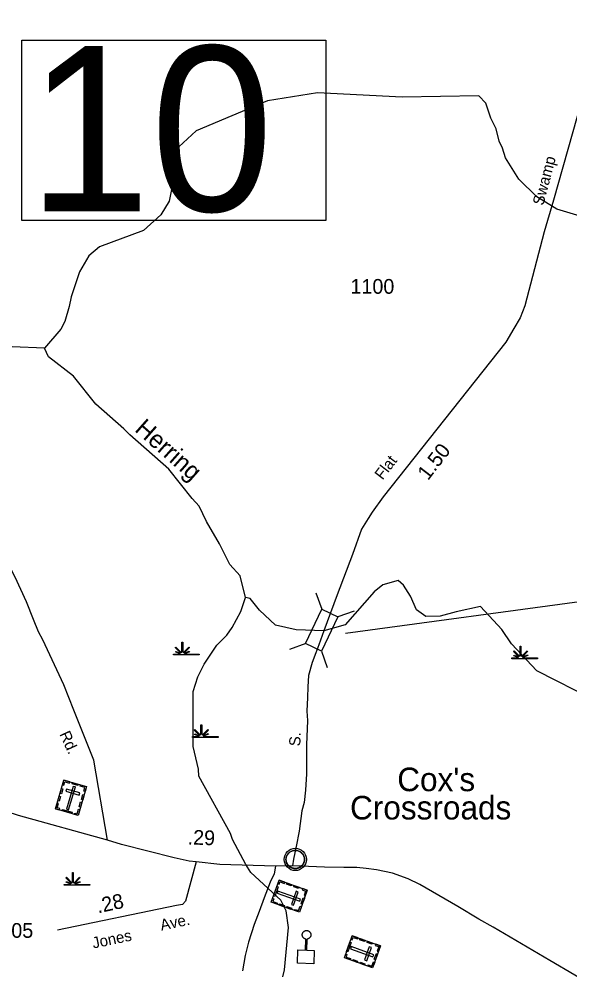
# Model space of a CAD drawing. Extents: x 2532689 to 2764727, y 536648 to 732970.
# Drawn here: x 2608460 to 2613131, y 594925 to 602992 of the extents above; entities that cross this region are included whole.
import ezdxf

# ---------------------------------------------------------------- set-up
doc = ezdxf.new("R2010")
doc.units = 0
for name, color, linetype in [('Exist Civil Demographics Community CELL', 7, 'Continuous'), ('Exist Civil Demographics Community Label', 7, 'Continuous'), ('Exist Civil Post Office CELL', 7, 'Continuous'), ('Exist Cultural Cemetery CELL', 7, 'Continuous'), ('Exist Hydrographic Creek Single Shore', 7, 'Continuous'), ('Exist Hydrographic Creek Single Shore Label', 7, 'Continuous'), ('Exist Hydrographic Swamp CELL', 7, 'Continuous'), ('Exist Road Primary NC Attributed', 7, 'Continuous'), ('Exist Road Primary NC Mileage Hundredths English Label', 7, 'Continuous'), ('Exist Road Secondary Mileage Hundredths English Label', 7, 'Continuous'), ('Exist Road Secondary Structure Standard Bridge CELL', 7, 'Continuous'), ('Exist Road Secondary Structure Standard Bridge Number Label', 7, 'Continuous'), ('Exist Road Secondary Type 10 Attributed', 7, 'Continuous'), ('Exist Road Secondary Type 51 Attributed', 7, 'Continuous'), ('Exist Road Secondary Type 51 Label', 7, 'Continuous'), ('Exist Road Secondary Type 51 Number Label', 7, 'Continuous')]:
    doc.layers.add(name, color=color, linetype=linetype)

msp = doc.modelspace()

# ---------------------------------------------------------------- linework, layer by layer
at = {"layer": 'Exist Civil Demographics Community CELL'}
msp.add_lwpolyline([(2610724.5, 595874.9), (2610725.5, 595880.5), (2610727.2, 595887.1), (2610730.2, 595894.3), (2610733.1, 595900), (2610736.4, 595905.7), (2610740.2, 595910.9), (2610744.1, 595915.2), (2610748.7, 595919.8), (2610754.3, 595924.4), (2610759.7, 595928.1), (2610764.6, 595930.9), (2610769.6, 595933.4), (2610775.1, 595935.7), (2610780.7, 595937.5), (2610785, 595938.7), (2610789.9, 595939.4), (2610794, 595940.1), (2610800.4, 595940.4), (2610804.8, 595940.3), (2610810.5, 595940), (2610815.4, 595939.3), (2610820.3, 595938.3), (2610825.3, 595936.9), (2610830.5, 595935), (2610837.1, 595932), (2610843.4, 595928.5), (2610848.4, 595925), (2610853.6, 595921), (2610856.9, 595917.9), (2610861, 595913.5), (2610864.9, 595908.8), (2610868, 595904.2), (2610871.1, 595899.2), (2610873.6, 595894), (2610875.6, 595889), (2610877.2, 595884), (2610878.4, 595879.4), (2610879.5, 595873.3), (2610880.2, 595868.6), (2610880.4, 595862.6), (2610880.2, 595856.9), (2610879.7, 595851.2), (2610878.7, 595845.7), (2610877.1, 595839.5), (2610875.2, 595833.7), (2610872.9, 595828.6), (2610869.8, 595822.6), (2610866.5, 595817.3), (2610863, 595812.6), (2610858.8, 595807.9), (2610853.5, 595802.9), (2610848.5, 595798.8), (2610843.5, 595795.3), (2610839.2, 595792.8), (2610832.3, 595789.6), (2610825.2, 595786.9), (2610819.2, 595785.4), (2610812.6, 595784.1), (2610808.2, 595783.6), (2610803.7, 595783.4), (2610798.1, 595783.4), (2610793.9, 595783.8), (2610788.2, 595784.5), (2610782.3, 595785.8), (2610777.7, 595787.1), (2610772.5, 595789), (2610768, 595791), (2610764, 595793.2), (2610757.2, 595797.3), (2610751.7, 595801.6), (2610746.7, 595806.1), (2610742.3, 595810.9), (2610739.1, 595814.9), (2610736.1, 595819.1), (2610732, 595826.2), (2610730.3, 595829.7), (2610728.6, 595833.7), (2610726, 595841.9), (2610724.5, 595849), (2610723.8, 595854.1), (2610723.4, 595860.5), (2610723.4, 595865.1), (2610723.9, 595871.6)], close=True, dxfattribs=at)
for centre, radius in [((2610802.1, 595862.5), 94.3), ((2610801.8, 595862.8), 76.7)]:
    msp.add_circle(centre, radius, dxfattribs=at)
at = {"layer": 'Exist Civil Post Office CELL'}
msp.add_lwpolyline([(2610892.7, 595186.9), (2610890, 595187.4), (2610887.2, 595188.1), (2610884.4, 595189.1), (2610881.8, 595190.2), (2610879.5, 595191.5), (2610877.5, 595192.8), (2610875.7, 595194), (2610873.6, 595195.8), (2610872.1, 595197.2), (2610870.5, 595199), (2610869, 595200.8), (2610867.7, 595202.5), (2610866.5, 595204.5), (2610865.4, 595206.6), (2610864.5, 595208.5), (2610863.6, 595210.4), (2610863.1, 595212.1), (2610862.5, 595214.1), (2610862, 595216.4), (2610861.7, 595218.5), (2610861.5, 595220.6), (2610861.5, 595222.9), (2610861.5, 595225.6), (2610861.8, 595227.8), (2610862.1, 595230), (2610862.7, 595232.6), (2610863.3, 595234.5), (2610864, 595236.5), (2610864.8, 595238.3), (2610865.6, 595239.9), (2610866.6, 595241.7), (2610867.8, 595243.5), (2610869.1, 595245.4), (2610871.2, 595247.8), (2610873, 595249.6), (2610874.7, 595251.1), (2610876.3, 595252.3), (2610877.9, 595253.5), (2610879.9, 595254.7), (2610881.7, 595255.7), (2610884, 595256.7), (2610886.2, 595257.5), (2610889.1, 595258.4), (2610891.7, 595258.9), (2610894.5, 595259.4), (2610897.2, 595259.5), (2610899.2, 595259.4), (2610902.1, 595259.3), (2610905, 595258.8), (2610907.6, 595258.2), (2610909.8, 595257.5), (2610911.8, 595256.7), (2610914.3, 595255.6), (2610916.5, 595254.4), (2610918.8, 595252.9), (2610921, 595251.3), (2610923.2, 595249.3), (2610925.1, 595247.4), (2610926.6, 595245.6), (2610927.7, 595244.1), (2610929.3, 595241.5), (2610930.4, 595239.6), (2610931.4, 595237.5), (2610932.2, 595235.4), (2610932.9, 595233.2), (2610933.6, 595230.7), (2610933.9, 595228.4), (2610934.3, 595225.7), (2610934.4, 595223.6), (2610934.4, 595221.3), (2610934.2, 595218.9), (2610933.9, 595216.9), (2610933.4, 595214.3), (2610932.7, 595212), (2610931.9, 595209.7), (2610931, 595207.5), (2610929.9, 595205.3), (2610928.6, 595203.2), (2610926.9, 595200.7), (2610925.3, 595198.9), (2610923.5, 595196.9), (2610921.1, 595194.8), (2610919.2, 595193.3), (2610917.4, 595192.1), (2610915, 595190.7), (2610912.8, 595189.7), (2610910.5, 595188.7), (2610908.6, 595188.1), (2610906.3, 595187.4), (2610903.7, 595186.9), (2610902, 595186.7), (2610900.7, 595186.6), (2610897.6, 595093.2), (2610963.1, 595091), (2610959.3, 594977.6), (2610820.3, 594982.3), (2610824, 595095.7), (2610889.6, 595093.5)], close=True, dxfattribs=at)
at = {"layer": 'Exist Cultural Cemetery CELL'}
for points in [[(2608841.1, 596536), (2609032.2, 596480.1), (2608960.7, 596235.7), (2608769.6, 596291.6)], [(2608828.9, 596494.4), (2608839.8, 596491.3), (2608848.9, 596522.2), (2608887.8, 596510.8), (2608890.9, 596521.4), (2608841.1, 596536)], [(2608912.2, 596515.2), (2608961.9, 596500.7), (2608958.7, 596489.7), (2608909, 596504.3)], [(2608808.1, 596423.3), (2608820.3, 596464.9), (2608831.2, 596461.7), (2608819, 596420.1)], [(2608861.2, 596459.2), (2608855.9, 596441.3), (2608968.9, 596408.3), (2608974.2, 596426.2)], [(2608937.5, 596477.3), (2608919.6, 596482.5), (2608862.6, 596287.9), (2608880.6, 596282.7)], [(2609020.1, 596438.5), (2609009.2, 596441.7), (2609018.2, 596472.6), (2608979.3, 596483.9), (2608982.4, 596494.6), (2609032.2, 596480.1)], [(2608789.2, 596358.8), (2608801.4, 596400.3), (2608812.3, 596397.1), (2608800.1, 596355.6)], [(2608970.1, 596308.3), (2608982.2, 596349.9), (2608993.1, 596346.7), (2608981, 596305.1)], [(2608988.6, 596371.6), (2609000.8, 596413.1), (2609011.7, 596409.9), (2608999.5, 596368.4)], [(2608801.4, 596282.4), (2608804.6, 596293.4), (2608783.5, 596299.6), (2608794.8, 596338.4), (2608784.1, 596341.5), (2608769.6, 596291.7)], [(2608828, 596286.5), (2608909.4, 596262.7), (2608906.2, 596251.8), (2608824.8, 596275.6)], [(2608928.9, 596245), (2608932.1, 596256.1), (2608953.2, 596249.9), (2608964.6, 596288.7), (2608975.3, 596285.5), (2608960.7, 596235.7)], [(2610904.4, 595601.4), (2610837.3, 595413.9), (2610597.6, 595499.7), (2610664.7, 595687.2)], [(2610656.1, 595629.2), (2610627.5, 595549.3), (2610616.8, 595553.1), (2610645.4, 595633)], [(2610653.6, 595656), (2610664.4, 595652.1), (2610671.8, 595672.8), (2610709.8, 595659.2), (2610713.6, 595669.7), (2610664.7, 595687.2)], [(2610730.5, 595663.6), (2610771.3, 595649), (2610767.5, 595638.3), (2610726.7, 595652.9)], [(2610793.8, 595641), (2610834.6, 595626.4), (2610830.8, 595615.6), (2610790, 595630.2)], [(2610840.1, 595508.6), (2610846.4, 595526.2), (2610655.4, 595594.5), (2610649.2, 595576.9)], [(2610826.6, 595585.9), (2610809, 595592.2), (2610769.3, 595481.3), (2610786.9, 595475)], [(2610863.6, 595616), (2610859.8, 595605.3), (2610890.1, 595594.4), (2610876.4, 595556.2), (2610886.9, 595552.5), (2610904.4, 595601.4)], [(2610608.7, 595530.9), (2610619.6, 595527), (2610612.1, 595506.3), (2610650.2, 595492.7), (2610646.4, 595482.2), (2610597.6, 595499.7)], [(2610669.5, 595486.1), (2610710.2, 595471.5), (2610706.4, 595460.8), (2610665.6, 595475.4)], [(2610731.5, 595463.8), (2610772.3, 595449.2), (2610768.5, 595438.5), (2610727.7, 595453.1)], [(2610796.5, 595428.5), (2610800.3, 595439.1), (2610830.6, 595428.3), (2610844.3, 595466.5), (2610854.7, 595462.7), (2610837.2, 595413.9)], [(2610879.4, 595531.6), (2610862, 595482.8), (2610851.2, 595486.7), (2610868.7, 595535.5)], [(2611525.2, 595129.8), (2611458.1, 594942.4), (2611218.4, 595028.2), (2611285.5, 595215.6)], [(2611276.9, 595157.6), (2611248.3, 595077.7), (2611237.6, 595081.6), (2611266.2, 595161.5)], [(2611274.4, 595184.5), (2611285.2, 595180.6), (2611292.6, 595201.3), (2611330.7, 595187.7), (2611334.4, 595198.2), (2611285.6, 595215.6)], [(2611351.3, 595192.1), (2611392.1, 595177.5), (2611388.3, 595166.8), (2611347.5, 595181.4)], [(2611414.6, 595169.4), (2611455.4, 595154.8), (2611451.6, 595144.1), (2611410.8, 595158.7)], [(2611484.4, 595144.4), (2611480.6, 595133.7), (2611510.9, 595122.9), (2611497.3, 595084.7), (2611507.7, 595080.9), (2611525.2, 595129.8)], [(2611229.6, 595059.4), (2611240.4, 595055.5), (2611233, 595034.8), (2611271, 595021.2), (2611267.3, 595010.7), (2611218.4, 595028.2)], [(2611460.9, 595037), (2611467.2, 595054.6), (2611276.3, 595123), (2611270, 595105.4)], [(2611447.4, 595114.3), (2611429.8, 595120.6), (2611390.1, 595009.8), (2611407.7, 595003.5)], [(2611500.2, 595060.1), (2611482.8, 595011.3), (2611472.1, 595015.1), (2611489.5, 595063.9)], [(2611290.3, 595014.5), (2611331.1, 594999.9), (2611327.2, 594989.2), (2611286.4, 595003.8)], [(2611352.3, 594992.3), (2611393.1, 594977.7), (2611389.3, 594967), (2611348.5, 594981.6)], [(2611417.3, 594956.9), (2611421.1, 594967.6), (2611451.4, 594956.7), (2611465.1, 594994.9), (2611475.6, 594991.2), (2611458.1, 594942.3)]]:
    msp.add_lwpolyline(points, close=True, dxfattribs=at)
at = {"layer": 'Exist Hydrographic Creek Single Shore'}
for points in [[(2613246.1, 601310.4), (2613019.1, 601380), (2612849.9, 601484.9), (2612697, 601633), (2612585, 601815.6), (2612557.9, 601896.6), (2612531.9, 601954.6), (2612505, 602061.9), (2612460.9, 602152.1), (2612416.9, 602278.3), (2612358, 602341.6), (2611708, 602328.4), (2610989.9, 602365.1), (2610565.9, 602298.7), (2609962.8, 602044.5), (2609815.8, 601907.2), (2609816.8, 601864.6), (2609734, 601447.5), (2609661, 601329.7), (2609513.9, 601199), (2609141.8, 601059.2), (2609052, 600983.3), (2608971.8, 600848.7), (2608900.8, 600635.7), (2608885.9, 600553), (2608846.9, 600426.7), (2608814.9, 600359.7), (2608676.9, 600199.9)], [(2608676.9, 600199.9), (2608400.9, 600211.7), (2607664.8, 600369.1), (2607356.8, 600330.4), (2606973.7, 600331.3), (2606705.8, 600359.8), (2606303.8, 600458.6), (2605992.8, 600593.8), (2605875.7, 600598.8)], [(2610379, 598085.3), (2610333.9, 598267.3), (2610248, 598365.7), (2610160.9, 598539.4), (2610048.9, 598728.6), (2609988, 598860.8), (2609927.9, 598924), (2609730.9, 599172.1), (2609399.9, 599464.1), (2609348.9, 599514.6), (2609110.8, 599725), (2608922.8, 599963.6), (2608710.9, 600125.7), (2608676.9, 600199.9)], [(2612553.8, 597813.8), (2612371.9, 598008.3), (2612165.1, 597963.8), (2612032, 597925.6), (2611907.9, 597923.9), (2611831, 597979.9), (2611778.9, 598095.9), (2611719.1, 598188.7), (2611676, 598229.7), (2611543.9, 598191.5), (2611469.9, 598132.7), (2611224.9, 597853.6), (2611043.6, 597802.8), (2610810.1, 597810.5), (2610633.9, 597849.4), (2610498, 597978.5), (2610420.9, 598077.1), (2610379, 598085.3)], [(2610220.7, 597765.2), (2610267.9, 597831.3), (2610339.9, 597965.6), (2610379, 598085.3)], [(2616087.3, 595239.6), (2615985.2, 595376.6), (2615663.2, 595596.8), (2615305.2, 595973), (2615202.1, 596119.8), (2614989.2, 596347.6), (2614726.2, 596560.3), (2614499.2, 596695.5), (2613920.1, 596875.7), (2613701.1, 596998.2), (2613338.2, 597213.3), (2612849.1, 597462.8), (2612636.1, 597690.6), (2612553.8, 597813.8)], [(2610656.1, 594708.2), (2610710, 594927.1), (2610744, 595286.3), (2610725, 595426.8), (2610681.1, 595516.9), (2610426, 595752.9), (2610382.9, 595820), (2610270, 596032.2), (2610252.9, 596084), (2609983.9, 596568.9), (2609982.9, 596627.9), (2609937, 596819.8), (2609935.9, 597286), (2609974.9, 597412.3), (2610030.9, 597519.7), (2610135.9, 597681.5), (2610220.7, 597765.2)]]:
    msp.add_lwpolyline(points, dxfattribs=at)
at = {"layer": 'Exist Hydrographic Swamp CELL'}
for points in [[(2609769.7, 597604.1), (2609822.3, 597604.1), (2609824.3, 597607.7), (2609786.1, 597622.6), (2609789, 597627.8), (2609826.7, 597612), (2609828.3, 597614.9), (2609783.9, 597659.4), (2609789, 597664.6), (2609834.3, 597619.1), (2609840.6, 597621.5), (2609840.6, 597704.6), (2609847.9, 597704.6), (2609847.8, 597621.5), (2609854.2, 597619.1), (2609899.5, 597664.6), (2609904.6, 597659.4), (2609860.2, 597614.9), (2609862.2, 597611.3), (2609903.1, 597629.9), (2609905.5, 597624.9), (2609864.6, 597607), (2609866.2, 597604.1), (2609987.2, 597604.1), (2609987.2, 597596.9), (2609769.7, 597596.9)], [(2612637.7, 597571.7), (2612690.3, 597571.8), (2612692.3, 597575.4), (2612654.1, 597590.2), (2612657, 597595.4), (2612694.7, 597579.6), (2612696.3, 597582.5), (2612651.9, 597627.1), (2612657, 597632.2), (2612702.3, 597586.7), (2612708.6, 597589.1), (2612708.6, 597672.2), (2612715.9, 597672.2), (2612715.9, 597589.1), (2612722.2, 597586.7), (2612767.5, 597632.2), (2612772.6, 597627.1), (2612728.2, 597582.5), (2612730.2, 597578.9), (2612771.1, 597597.5), (2612773.5, 597592.5), (2612732.6, 597574.7), (2612734.2, 597571.8), (2612855.2, 597571.7), (2612855.2, 597564.6), (2612637.7, 597564.6)], [(2609930.6, 596904.1), (2609983.2, 596904.2), (2609985.2, 596907.8), (2609947, 596922.6), (2609949.9, 596927.8), (2609987.6, 596912), (2609989.2, 596914.9), (2609944.8, 596959.5), (2609949.9, 596964.6), (2609995.2, 596919.1), (2610001.5, 596921.5), (2610001.5, 597004.6), (2610008.7, 597004.6), (2610008.7, 596921.5), (2610015.1, 596919.1), (2610060.4, 596964.6), (2610065.5, 596959.5), (2610021.1, 596914.9), (2610023.1, 596911.3), (2610064, 596929.9), (2610066.4, 596924.9), (2610025.4, 596907.1), (2610027, 596904.2), (2610148.1, 596904.1), (2610148.1, 596897), (2609930.6, 596897)], [(2608841.9, 595650.3), (2608894.5, 595650.4), (2608896.5, 595654), (2608858.2, 595668.8), (2608861.1, 595674), (2608898.9, 595658.3), (2608900.5, 595661.1), (2608856, 595705.7), (2608861.2, 595710.8), (2608906.4, 595665.3), (2608912.8, 595667.7), (2608912.8, 595750.8), (2608920, 595750.8), (2608920, 595667.7), (2608926.3, 595665.3), (2608971.6, 595710.8), (2608976.8, 595705.7), (2608932.3, 595661.1), (2608934.3, 595657.5), (2608975.2, 595676.1), (2608977.7, 595671.1), (2608936.7, 595653.3), (2608938.3, 595650.4), (2609059.4, 595650.3), (2609059.4, 595643.2), (2608841.9, 595643.2)]]:
    msp.add_lwpolyline(points, close=True, dxfattribs=at)
at = {"layer": 'Exist Road Primary NC Attributed'}
for points in [[(2609209, 596025.1), (2608455.4, 596236.7), (2607613, 596505.8)], [(2609962.7, 595841.6), (2609901.3, 595846.8), (2609775.4, 595874.8), (2609327.8, 595990.1), (2609209, 596025.1)], [(2610634.4, 595806.5), (2610162.3, 595819.9), (2609962.7, 595841.6)], [(2610780, 595809.6), (2610634.4, 595806.5)], [(2618622, 593002.4), (2615679, 593509), (2615482.1, 593555.2), (2615414.5, 593579.8), (2615214.6, 593678.2), (2614737.8, 593959.1), (2614095.5, 594337.4), (2613597.3, 594630.6), (2612960.1, 595005.8), (2612478.8, 595288.8), (2612359.9, 595356.5), (2612179.4, 595464.1), (2611858.5, 595648.6), (2611760.1, 595697.9), (2611626.3, 595745), (2611490, 595774.7), (2611402.8, 595786), (2611324.9, 595793.2), (2611212.7, 595795.3), (2611050.7, 595798.3), (2610780, 595809.6)]]:
    msp.add_lwpolyline(points, dxfattribs=at)
at = {"layer": 'Exist Road Secondary Structure Standard Bridge CELL'}
for p, q in [((2610977.7, 598124.1), (2611026.9, 597985.4)), ((2611301.4, 597969.9), (2611162.8, 597920.7)), ((2610890.8, 597693.3), (2610752.1, 597644.1)), ((2611023.6, 597630.1), (2611072.8, 597491.4))]:
    msp.add_line(p, q, dxfattribs=at)
msp.add_lwpolyline([(2611162.8, 597920.7), (2611024.2, 597629.8), (2610888.3, 597694.5), (2611026.9, 597985.4)], close=True, dxfattribs=at)
at = {"layer": 'Exist Road Secondary Structure Standard Bridge Number Label'}
msp.add_line((2611228.4, 597781.2), (2616649.6, 598515.7), dxfattribs=at)
msp.add_lwpolyline([(2608483.9, 602812.1), (2611060.5, 602812.1), (2611060.5, 601282.9), (2608483.9, 601282.9)], close=True, dxfattribs=at)
at = {"layer": 'Exist Road Secondary Type 10 Attributed'}
msp.add_lwpolyline([(2609962.7, 595841.6), (2609870.6, 595508.1), (2609847.1, 595481.5), (2609795.2, 595472.5), (2608785.3, 595261.3)], dxfattribs=at)
at = {"layer": 'Exist Road Secondary Type 51 Attributed'}
for points in [[(2613499, 602992.2), (2613423.2, 602902.6), (2613368.1, 602792.4), (2613192.5, 602165.2), (2612992.8, 601455.4), (2612913.6, 601186.7), (2612748.3, 600559.6), (2612710.4, 600456.2), (2612655.3, 600366.6), (2612586.4, 600249.5), (2611546.4, 598940.1), (2611453.4, 598809.2), (2611419, 598754), (2611363.9, 598664.5), (2611288.1, 598450.8), (2611157.3, 598106.3), (2611043.6, 597802.8)], [(2609209, 596025.1), (2609093.6, 596703.5), (2608925.5, 597130.1), (2608839.5, 597342.4), (2608660.5, 597724.6), (2608625.4, 597793.1), (2608582, 597897.2), (2608522.6, 598049), (2608428.2, 598257), (2608303.2, 598498.5), (2608042.8, 598897), (2607906, 599138.4), (2607822.4, 599218.4), (2607757.1, 599265), (2607693.8, 599329.8), (2607431.5, 599442.3), (2607282.5, 599489.5), (2607101.9, 599521.6), (2606765.8, 599616.7), (2606743.2, 599648.2), (2606690.8, 599739.5), (2606677, 599966.9), (2606683.9, 600159.9), (2606705.8, 600359.8)], [(2611043.6, 597802.8), (2611001.2, 597682), (2610976.7, 597615.3), (2610944.5, 597534.6), (2610914.8, 597424), (2610908.6, 597325.9), (2610904.7, 597235.8), (2610901.1, 597121.7), (2610906.3, 597042), (2610897.7, 596833.4), (2610897.7, 596707.7), (2610897.7, 596587.6), (2610889.2, 596450.5), (2610877.7, 596344.7), (2610858.5, 596274.6), (2610834.9, 596101.8), (2610808.7, 595971.6), (2610787.9, 595863.8), (2610780, 595809.6)], [(2610634.4, 595806.5), (2610623.6, 595740.8), (2610590.3, 595670.4), (2610538.2, 595537.3), (2610495.3, 595420.1), (2610452.5, 595311.5), (2610406.8, 595160.1), (2610378.2, 595048.6), (2610353.9, 594918.6)]]:
    msp.add_lwpolyline(points, dxfattribs=at)

# ---------------------------------------------------------------- texts
at = {"layer": 'Exist Civil Demographics Community Label'}
for s, p in [("Cox's", (2611666.8, 596441.6)), ('Crossroads', (2611266.7, 596201.6))]:
    msp.add_text(s, height=200, dxfattribs=at).set_placement(p)
at = {"layer": 'Exist Hydrographic Creek Single Shore Label'}
msp.add_text('Herring', height=150, rotation=318.57868, dxfattribs=at).set_placement((2609432.7, 599500.8))
at = {"layer": 'Exist Road Primary NC Mileage Hundredths English Label'}
msp.add_text('.29', height=125, rotation=358.08678, dxfattribs=at).set_placement((2609887.9, 595989.9))
at = {"layer": 'Exist Road Secondary Mileage Hundredths English Label'}
for s, rotation, p in [('1.50', 52.52507, (2611927.6, 599071.9)), ('.28', 12.13986, (2609129.7, 595404.9))]:
    msp.add_text(s, height=125, rotation=rotation, dxfattribs=at).set_placement(p)
at = {"layer": 'Exist Road Secondary Structure Standard Bridge Number Label'}
msp.add_text('10', height=1400, dxfattribs=at).set_placement((2608534.1, 601362))
at = {"layer": 'Exist Road Secondary Type 51 Label'}
for s, rotation, p in [('Swamp', 75.22408, (2612904.7, 601404.7)), ('Flat', 52.52506, (2611542.2, 599076)), ('Rd.', 294.61549, (2608800.6, 596926.1)), ('S.', 87.53666, (2610844.3, 596821.4)), ('Ave.', 11.81234, (2609667.2, 595258.2)), ('Jones', 11.81234, (2609090.2, 595106.1))]:
    msp.add_text(s, height=95, rotation=rotation, dxfattribs=at).set_placement(p)
at = {"layer": 'Exist Road Secondary Type 51 Number Label'}
for s, p in [('1100', (2611270.2, 600661.5)), ('1105', (2608208.4, 595197.7))]:
    msp.add_text(s, height=125, dxfattribs=at).set_placement(p)

doc.saveas('drawing.dxf')
